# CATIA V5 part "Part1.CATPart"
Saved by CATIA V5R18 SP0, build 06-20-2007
Part number: Part1
Bounding box of the stored display mesh (mm): x -100 to 100, y -50 to 50, z 0 to 10
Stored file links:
  D:\Shriniwas\v5_r19\c16_CAT_v5r19\c16_Part\Planer Joint\Part1.CATPart
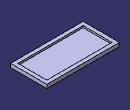
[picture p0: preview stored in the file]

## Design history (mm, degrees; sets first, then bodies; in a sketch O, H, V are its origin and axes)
Body1 (main body)
  Sketch1 on xy-plane, origin (0, 0, 0), H (1, 0, 0), V (0, 1, 0)
    line L1 (100, 50) -> (100, -50)
    line L2 (100, -50) -> (-100, -50)
    line L3 (-100, -50) -> (-100, 50)
    line L4 (-100, 50) -> (100, 50)
    line L5 (90, 40) -> (90, -40)
    line L6 (90, -40) -> (-90, -40)
    line L7 (-90, -40) -> (-90, 40)
    line L8 (-90, 40) -> (90, 40)
    length L4 = 200
    length L1 = 100
    length L8 = 180
    length L5 = 80
    vertical: L1 V, L3 V, L5 V, L7 V
    horizontal: L2 H, L4 H, L6 H, L8 H
    equidistance: L1 L3 O, L2 L4 O, L5 L7 O, L6 L8 O
  MultiPad1: profile Sketch1, domains (length 5; length 10)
